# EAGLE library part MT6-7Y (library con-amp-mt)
AMP MT6 CONNECTOR
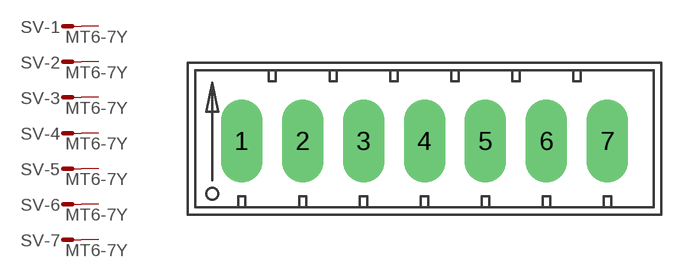
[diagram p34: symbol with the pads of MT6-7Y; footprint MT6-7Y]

Designator prefix SV; gates -1=MA -2=MA -3=MA -4=MA -5=MA -6=MA -7=MA

## MT6-7Y (OC_FARNELL: unknown; OC_NEWARK: unknown)  [MT6-7Y]
1  -1:S  pas
2  -2:S  pas
3  -3:S  pas
4  -4:S  pas
5  -5:S  pas
6  -6:S  pas
7  -7:S  pas

## Footprint MT6-7Y (pad centres in mm)
AMP MT6 CONNECTOR
drill 1.803 long: 1 -11.887,0; 2 -7.925,0; 3 -3.962,0; 4 0,0; 5 3.962,0; 6 7.925,0; 7 11.887,0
